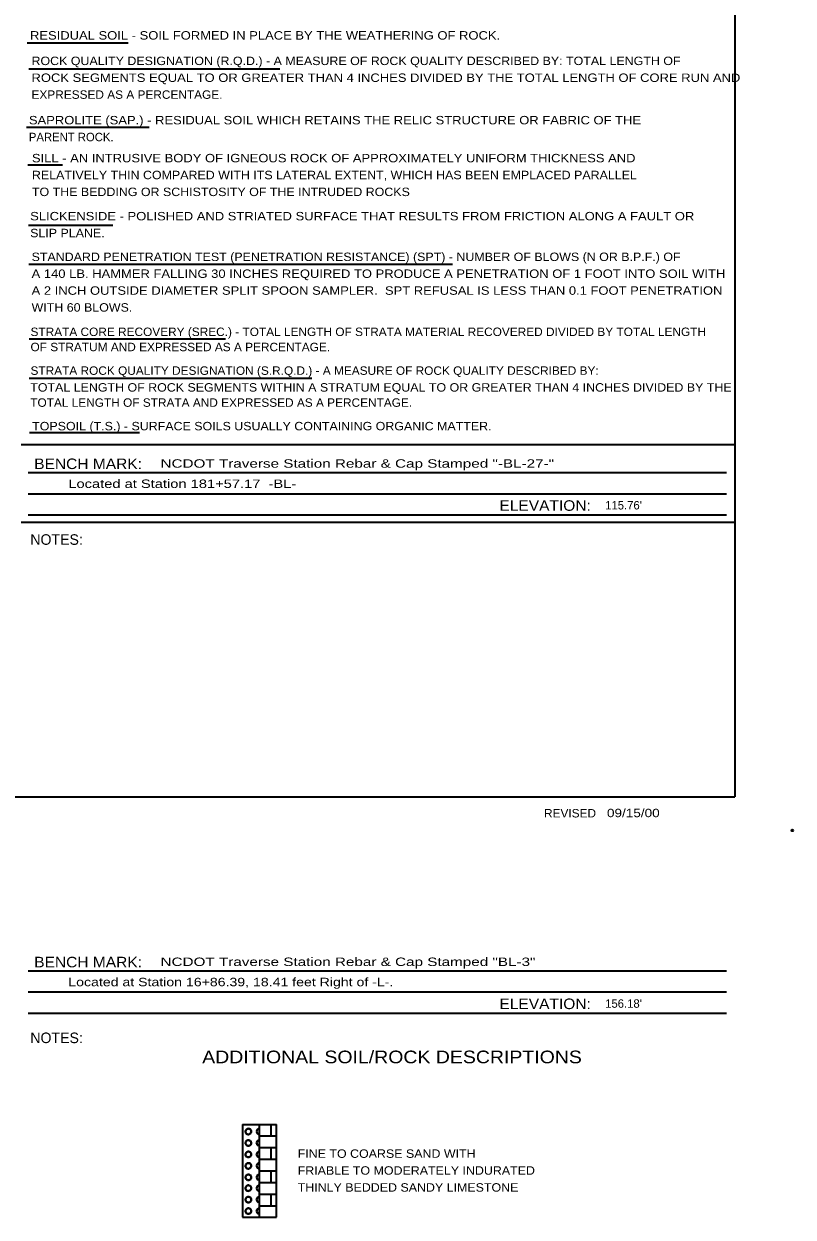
# Model space of a CAD drawing. Extents: x 2137492.6 to 2137529.1, y 2137475.8 to 2137563.
# Drawn here: x 2137519.94 to 2137529.06, y 2137534.75 to 2137548.89 of the extents above; entities that cross this region are included whole.
import ezdxf
from ezdxf.enums import TextEntityAlignment as Align

# ---------------------------------------------------------------- set-up
doc = ezdxf.new("R2010")
doc.units = 0
doc.header["$LTSCALE"] = 0.04
doc.header["$PDMODE"] = 32
doc.header["$PDSIZE"] = 0.02
doc.layers.add('1', color=7, linetype='Continuous', lineweight=35)
doc.layers.add('27', color=7, linetype='Continuous', lineweight=40)

msp = doc.modelspace()

# ---------------------------------------------------------------- linework, layer by layer
at = {"layer": '1'}
for p, q in [((2137528.371, 2137561.718), (2137528.371, 2137539.727)), ((2137528.371, 2137558.425), (2137528.371, 2137539.727)), ((2137519.985, 2137548.666), (2137521.181, 2137548.666)), ((2137520.003, 2137548.359), (2137522.976, 2137548.359)), ((2137519.977, 2137547.665), (2137521.431, 2137547.665)), ((2137519.993, 2137547.219), (2137520.402, 2137547.219)), ((2137519.998, 2137546.504), (2137521, 2137546.504)), ((2137520.003, 2137546.04), (2137525.022, 2137546.04)), ((2137520.008, 2137545.156), (2137522.335, 2137545.156)), ((2137520.006, 2137544.692), (2137523.357, 2137544.692)), ((2137520.011, 2137544.048), (2137521.314, 2137544.048)), ((2137519.912, 2137543.903), (2137528.371, 2137543.903)), ((2137519.994, 2137543.571), (2137528.27, 2137543.571)), ((2137519.994, 2137543.321), (2137528.27, 2137543.321)), ((2137519.912, 2137542.983), (2137528.371, 2137542.983)), ((2137519.994, 2137543.071), (2137528.27, 2137543.071)), ((2137519.994, 2137537.664), (2137528.27, 2137537.664)), ((2137519.994, 2137537.414), (2137528.27, 2137537.414)), ((2137519.994, 2137537.164), (2137528.27, 2137537.164)), ((2137522.537, 2137535.845), (2137522.937, 2137535.845)), ((2137522.537, 2137535.845), (2137522.537, 2137534.745)), ((2137522.737, 2137534.745), (2137522.737, 2137535.845)), ((2137522.875, 2137535.707), (2137522.875, 2137535.845)), ((2137522.937, 2137534.745), (2137522.937, 2137535.845)), ((2137522.737, 2137535.707), (2137522.937, 2137535.707)), ((2137522.737, 2137535.569), (2137522.937, 2137535.569)), ((2137522.875, 2137535.432), (2137522.875, 2137535.569)), ((2137522.737, 2137535.432), (2137522.937, 2137535.432)), ((2137522.737, 2137535.294), (2137522.937, 2137535.294)), ((2137522.875, 2137535.156), (2137522.875, 2137535.294)), ((2137522.737, 2137535.156), (2137522.937, 2137535.156)), ((2137522.737, 2137535.018), (2137522.937, 2137535.018)), ((2137522.875, 2137534.88), (2137522.875, 2137535.018)), ((2137522.737, 2137534.88), (2137522.937, 2137534.88)), ((2137522.537, 2137534.745), (2137522.937, 2137534.745))]:
    msp.add_line(p, q, dxfattribs=at)
msp.add_lwpolyline([(2137493.171, 2137561.718), (2137493.171, 2137539.727), (2137528.371, 2137539.727)], dxfattribs=at)
msp.add_point((2137529.05, 2137539.329), dxfattribs=at)
at = {"layer": '27'}
for points in [[(2137522.639, 2137535.76), (2137522.638, 2137535.765), (2137522.637, 2137535.77), (2137522.635, 2137535.775), (2137522.632, 2137535.78), (2137522.629, 2137535.784), (2137522.625, 2137535.787), (2137522.62, 2137535.79), (2137522.615, 2137535.792), (2137522.61, 2137535.793), (2137522.605, 2137535.794), (2137522.6, 2137535.793), (2137522.595, 2137535.792), (2137522.59, 2137535.79), (2137522.585, 2137535.787), (2137522.581, 2137535.784), (2137522.578, 2137535.78), (2137522.575, 2137535.776), (2137522.573, 2137535.771), (2137522.571, 2137535.766), (2137522.571, 2137535.76), (2137522.571, 2137535.755), (2137522.572, 2137535.75), (2137522.574, 2137535.745), (2137522.577, 2137535.74), (2137522.58, 2137535.736), (2137522.584, 2137535.733), (2137522.589, 2137535.73), (2137522.593, 2137535.728), (2137522.599, 2137535.726), (2137522.604, 2137535.726), (2137522.609, 2137535.726), (2137522.614, 2137535.727), (2137522.619, 2137535.729), (2137522.624, 2137535.732), (2137522.628, 2137535.735), (2137522.632, 2137535.739), (2137522.634, 2137535.743), (2137522.637, 2137535.748), (2137522.638, 2137535.753), (2137522.639, 2137535.759)], [(2137522.639, 2137535.624), (2137522.638, 2137535.629), (2137522.637, 2137535.634), (2137522.635, 2137535.639), (2137522.632, 2137535.644), (2137522.629, 2137535.648), (2137522.625, 2137535.651), (2137522.62, 2137535.654), (2137522.615, 2137535.656), (2137522.61, 2137535.657), (2137522.605, 2137535.658), (2137522.6, 2137535.658), (2137522.595, 2137535.656), (2137522.59, 2137535.654), (2137522.585, 2137535.652), (2137522.581, 2137535.648), (2137522.578, 2137535.644), (2137522.575, 2137535.64), (2137522.573, 2137535.635), (2137522.571, 2137535.63), (2137522.571, 2137535.625), (2137522.571, 2137535.619), (2137522.572, 2137535.614), (2137522.574, 2137535.609), (2137522.577, 2137535.605), (2137522.58, 2137535.6), (2137522.584, 2137535.597), (2137522.589, 2137535.594), (2137522.593, 2137535.592), (2137522.599, 2137535.591), (2137522.604, 2137535.59), (2137522.609, 2137535.59), (2137522.614, 2137535.591), (2137522.619, 2137535.593), (2137522.624, 2137535.596), (2137522.628, 2137535.599), (2137522.632, 2137535.603), (2137522.634, 2137535.608), (2137522.637, 2137535.612), (2137522.638, 2137535.618), (2137522.639, 2137535.623)], [(2137522.639, 2137535.488), (2137522.638, 2137535.494), (2137522.637, 2137535.499), (2137522.635, 2137535.504), (2137522.632, 2137535.508), (2137522.629, 2137535.512), (2137522.625, 2137535.516), (2137522.62, 2137535.518), (2137522.615, 2137535.52), (2137522.61, 2137535.522), (2137522.605, 2137535.522), (2137522.6, 2137535.522), (2137522.595, 2137535.521), (2137522.59, 2137535.519), (2137522.585, 2137535.516), (2137522.581, 2137535.513), (2137522.578, 2137535.509), (2137522.575, 2137535.504), (2137522.573, 2137535.499), (2137522.571, 2137535.494), (2137522.571, 2137535.489), (2137522.571, 2137535.484), (2137522.572, 2137535.478), (2137522.574, 2137535.473), (2137522.577, 2137535.469), (2137522.58, 2137535.465), (2137522.584, 2137535.461), (2137522.589, 2137535.458), (2137522.593, 2137535.456), (2137522.599, 2137535.455), (2137522.604, 2137535.454), (2137522.609, 2137535.455), (2137522.614, 2137535.456), (2137522.619, 2137535.458), (2137522.624, 2137535.46), (2137522.628, 2137535.463), (2137522.632, 2137535.467), (2137522.634, 2137535.472), (2137522.637, 2137535.477), (2137522.638, 2137535.482), (2137522.639, 2137535.487)], [(2137522.639, 2137535.352), (2137522.638, 2137535.358), (2137522.637, 2137535.363), (2137522.635, 2137535.368), (2137522.632, 2137535.372), (2137522.629, 2137535.376), (2137522.625, 2137535.38), (2137522.62, 2137535.383), (2137522.615, 2137535.385), (2137522.61, 2137535.386), (2137522.605, 2137535.386), (2137522.6, 2137535.386), (2137522.595, 2137535.385), (2137522.59, 2137535.383), (2137522.585, 2137535.38), (2137522.581, 2137535.377), (2137522.578, 2137535.373), (2137522.575, 2137535.368), (2137522.573, 2137535.363), (2137522.571, 2137535.358), (2137522.571, 2137535.353), (2137522.571, 2137535.348), (2137522.572, 2137535.343), (2137522.574, 2137535.338), (2137522.577, 2137535.333), (2137522.58, 2137535.329), (2137522.584, 2137535.325), (2137522.589, 2137535.323), (2137522.593, 2137535.32), (2137522.599, 2137535.319), (2137522.604, 2137535.319), (2137522.609, 2137535.319), (2137522.614, 2137535.32), (2137522.619, 2137535.322), (2137522.624, 2137535.324), (2137522.628, 2137535.328), (2137522.632, 2137535.332), (2137522.634, 2137535.336), (2137522.637, 2137535.341), (2137522.638, 2137535.346), (2137522.639, 2137535.351)], [(2137522.639, 2137535.217), (2137522.638, 2137535.222), (2137522.637, 2137535.227), (2137522.635, 2137535.232), (2137522.632, 2137535.237), (2137522.629, 2137535.241), (2137522.625, 2137535.244), (2137522.62, 2137535.247), (2137522.615, 2137535.249), (2137522.61, 2137535.25), (2137522.605, 2137535.251), (2137522.6, 2137535.25), (2137522.595, 2137535.249), (2137522.59, 2137535.247), (2137522.585, 2137535.244), (2137522.581, 2137535.241), (2137522.578, 2137535.237), (2137522.575, 2137535.233), (2137522.573, 2137535.228), (2137522.571, 2137535.223), (2137522.571, 2137535.217), (2137522.571, 2137535.212), (2137522.572, 2137535.207), (2137522.574, 2137535.202), (2137522.577, 2137535.197), (2137522.58, 2137535.193), (2137522.584, 2137535.19), (2137522.589, 2137535.187), (2137522.593, 2137535.185), (2137522.599, 2137535.183), (2137522.604, 2137535.183), (2137522.609, 2137535.183), (2137522.614, 2137535.184), (2137522.619, 2137535.186), (2137522.624, 2137535.189), (2137522.628, 2137535.192), (2137522.632, 2137535.196), (2137522.634, 2137535.2), (2137522.637, 2137535.205), (2137522.638, 2137535.21), (2137522.639, 2137535.216)], [(2137522.639, 2137535.088), (2137522.638, 2137535.094), (2137522.637, 2137535.099), (2137522.635, 2137535.104), (2137522.632, 2137535.108), (2137522.629, 2137535.112), (2137522.625, 2137535.116), (2137522.62, 2137535.118), (2137522.615, 2137535.12), (2137522.61, 2137535.122), (2137522.605, 2137535.122), (2137522.6, 2137535.122), (2137522.595, 2137535.121), (2137522.59, 2137535.119), (2137522.585, 2137535.116), (2137522.581, 2137535.113), (2137522.578, 2137535.109), (2137522.575, 2137535.104), (2137522.573, 2137535.099), (2137522.571, 2137535.094), (2137522.571, 2137535.089), (2137522.571, 2137535.084), (2137522.572, 2137535.078), (2137522.574, 2137535.073), (2137522.577, 2137535.069), (2137522.58, 2137535.065), (2137522.584, 2137535.061), (2137522.589, 2137535.058), (2137522.593, 2137535.056), (2137522.599, 2137535.055), (2137522.604, 2137535.054), (2137522.609, 2137535.055), (2137522.614, 2137535.056), (2137522.619, 2137535.058), (2137522.624, 2137535.06), (2137522.628, 2137535.063), (2137522.632, 2137535.067), (2137522.634, 2137535.072), (2137522.637, 2137535.077), (2137522.638, 2137535.082), (2137522.639, 2137535.087)], [(2137522.639, 2137534.952), (2137522.638, 2137534.958), (2137522.637, 2137534.963), (2137522.635, 2137534.968), (2137522.632, 2137534.972), (2137522.629, 2137534.976), (2137522.625, 2137534.98), (2137522.62, 2137534.983), (2137522.615, 2137534.985), (2137522.61, 2137534.986), (2137522.605, 2137534.986), (2137522.6, 2137534.986), (2137522.595, 2137534.985), (2137522.59, 2137534.983), (2137522.585, 2137534.98), (2137522.581, 2137534.977), (2137522.578, 2137534.973), (2137522.575, 2137534.968), (2137522.573, 2137534.963), (2137522.571, 2137534.958), (2137522.571, 2137534.953), (2137522.571, 2137534.948), (2137522.572, 2137534.943), (2137522.574, 2137534.938), (2137522.577, 2137534.933), (2137522.58, 2137534.929), (2137522.584, 2137534.925), (2137522.589, 2137534.923), (2137522.593, 2137534.92), (2137522.599, 2137534.919), (2137522.604, 2137534.919), (2137522.609, 2137534.919), (2137522.614, 2137534.92), (2137522.619, 2137534.922), (2137522.624, 2137534.924), (2137522.628, 2137534.928), (2137522.632, 2137534.932), (2137522.634, 2137534.936), (2137522.637, 2137534.941), (2137522.638, 2137534.946), (2137522.639, 2137534.951)], [(2137522.639, 2137534.817), (2137522.638, 2137534.822), (2137522.637, 2137534.827), (2137522.635, 2137534.832), (2137522.632, 2137534.837), (2137522.629, 2137534.841), (2137522.625, 2137534.844), (2137522.62, 2137534.847), (2137522.615, 2137534.849), (2137522.61, 2137534.85), (2137522.605, 2137534.851), (2137522.6, 2137534.85), (2137522.595, 2137534.849), (2137522.59, 2137534.847), (2137522.585, 2137534.844), (2137522.581, 2137534.841), (2137522.578, 2137534.837), (2137522.575, 2137534.833), (2137522.573, 2137534.828), (2137522.571, 2137534.823), (2137522.571, 2137534.817), (2137522.571, 2137534.812), (2137522.572, 2137534.807), (2137522.574, 2137534.802), (2137522.577, 2137534.797), (2137522.58, 2137534.793), (2137522.584, 2137534.79), (2137522.589, 2137534.787), (2137522.593, 2137534.785), (2137522.599, 2137534.783), (2137522.604, 2137534.783), (2137522.609, 2137534.783), (2137522.614, 2137534.784), (2137522.619, 2137534.786), (2137522.624, 2137534.789), (2137522.628, 2137534.792), (2137522.632, 2137534.796), (2137522.634, 2137534.8), (2137522.637, 2137534.805), (2137522.638, 2137534.81), (2137522.639, 2137534.816)]]:
    msp.add_lwpolyline(points, close=True, dxfattribs=at)
for points in [[(2137522.737, 2137535.794), (2137522.732, 2137535.793), (2137522.727, 2137535.792), (2137522.722, 2137535.79), (2137522.718, 2137535.787), (2137522.713, 2137535.784), (2137522.71, 2137535.78), (2137522.707, 2137535.776), (2137522.705, 2137535.771), (2137522.704, 2137535.766), (2137522.703, 2137535.76), (2137522.704, 2137535.755), (2137522.705, 2137535.75), (2137522.707, 2137535.745), (2137522.709, 2137535.74), (2137522.713, 2137535.736), (2137522.717, 2137535.733), (2137522.721, 2137535.73), (2137522.726, 2137535.728), (2137522.731, 2137535.726), (2137522.736, 2137535.726), (2137522.737, 2137535.726)], [(2137522.737, 2137535.658), (2137522.732, 2137535.658), (2137522.727, 2137535.656), (2137522.722, 2137535.654), (2137522.718, 2137535.652), (2137522.713, 2137535.648), (2137522.71, 2137535.644), (2137522.707, 2137535.64), (2137522.705, 2137535.635), (2137522.704, 2137535.63), (2137522.703, 2137535.625), (2137522.704, 2137535.619), (2137522.705, 2137535.614), (2137522.707, 2137535.609), (2137522.709, 2137535.605), (2137522.713, 2137535.6), (2137522.717, 2137535.597), (2137522.721, 2137535.594), (2137522.726, 2137535.592), (2137522.731, 2137535.591), (2137522.736, 2137535.59), (2137522.737, 2137535.59)], [(2137522.737, 2137535.522), (2137522.732, 2137535.522), (2137522.727, 2137535.521), (2137522.722, 2137535.519), (2137522.718, 2137535.516), (2137522.713, 2137535.513), (2137522.71, 2137535.509), (2137522.707, 2137535.504), (2137522.705, 2137535.499), (2137522.704, 2137535.494), (2137522.703, 2137535.489), (2137522.704, 2137535.484), (2137522.705, 2137535.478), (2137522.707, 2137535.473), (2137522.709, 2137535.469), (2137522.713, 2137535.465), (2137522.717, 2137535.461), (2137522.721, 2137535.458), (2137522.726, 2137535.456), (2137522.731, 2137535.455), (2137522.736, 2137535.454), (2137522.737, 2137535.454)], [(2137522.737, 2137535.386), (2137522.732, 2137535.386), (2137522.727, 2137535.385), (2137522.722, 2137535.383), (2137522.718, 2137535.38), (2137522.713, 2137535.377), (2137522.71, 2137535.373), (2137522.707, 2137535.368), (2137522.705, 2137535.363), (2137522.704, 2137535.358), (2137522.703, 2137535.353), (2137522.704, 2137535.348), (2137522.705, 2137535.343), (2137522.707, 2137535.338), (2137522.709, 2137535.333), (2137522.713, 2137535.329), (2137522.717, 2137535.325), (2137522.721, 2137535.323), (2137522.726, 2137535.32), (2137522.731, 2137535.319), (2137522.736, 2137535.319), (2137522.737, 2137535.319)], [(2137522.737, 2137535.251), (2137522.732, 2137535.25), (2137522.727, 2137535.249), (2137522.722, 2137535.247), (2137522.718, 2137535.244), (2137522.713, 2137535.241), (2137522.71, 2137535.237), (2137522.707, 2137535.233), (2137522.705, 2137535.228), (2137522.704, 2137535.223), (2137522.703, 2137535.217), (2137522.704, 2137535.212), (2137522.705, 2137535.207), (2137522.707, 2137535.202), (2137522.709, 2137535.197), (2137522.713, 2137535.193), (2137522.717, 2137535.19), (2137522.721, 2137535.187), (2137522.726, 2137535.185), (2137522.731, 2137535.183), (2137522.736, 2137535.183), (2137522.737, 2137535.183)], [(2137522.737, 2137535.122), (2137522.732, 2137535.122), (2137522.727, 2137535.121), (2137522.722, 2137535.119), (2137522.718, 2137535.116), (2137522.713, 2137535.113), (2137522.71, 2137535.109), (2137522.707, 2137535.104), (2137522.705, 2137535.099), (2137522.704, 2137535.094), (2137522.703, 2137535.089), (2137522.704, 2137535.084), (2137522.705, 2137535.078), (2137522.707, 2137535.073), (2137522.709, 2137535.069), (2137522.713, 2137535.065), (2137522.717, 2137535.061), (2137522.721, 2137535.058), (2137522.726, 2137535.056), (2137522.731, 2137535.055), (2137522.736, 2137535.054), (2137522.737, 2137535.054)], [(2137522.737, 2137534.986), (2137522.732, 2137534.986), (2137522.727, 2137534.985), (2137522.722, 2137534.983), (2137522.718, 2137534.98), (2137522.713, 2137534.977), (2137522.71, 2137534.973), (2137522.707, 2137534.968), (2137522.705, 2137534.963), (2137522.704, 2137534.958), (2137522.703, 2137534.953), (2137522.704, 2137534.948), (2137522.705, 2137534.943), (2137522.707, 2137534.938), (2137522.709, 2137534.933), (2137522.713, 2137534.929), (2137522.717, 2137534.925), (2137522.721, 2137534.923), (2137522.726, 2137534.92), (2137522.731, 2137534.919), (2137522.736, 2137534.919), (2137522.737, 2137534.919)], [(2137522.737, 2137534.851), (2137522.732, 2137534.85), (2137522.727, 2137534.849), (2137522.722, 2137534.847), (2137522.718, 2137534.844), (2137522.713, 2137534.841), (2137522.71, 2137534.837), (2137522.707, 2137534.833), (2137522.705, 2137534.828), (2137522.704, 2137534.823), (2137522.703, 2137534.817), (2137522.704, 2137534.812), (2137522.705, 2137534.807), (2137522.707, 2137534.802), (2137522.709, 2137534.797), (2137522.713, 2137534.793), (2137522.717, 2137534.79), (2137522.721, 2137534.787), (2137522.726, 2137534.785), (2137522.731, 2137534.783), (2137522.736, 2137534.783), (2137522.737, 2137534.783)]]:
    msp.add_lwpolyline(points, dxfattribs=at)

# ---------------------------------------------------------------- texts
at = {"layer": '1'}
for s, height, width, p in [('RESIDUAL SOIL - SOIL FORMED IN PLACE BY THE WEATHERING OF ROCK.', 0.1, 1.15, (2137520.017, 2137548.704)), ('ROCK QUALITY DESIGNATION (R.Q.D.) - A MEASURE OF ROCK QUALITY DESCRIBED BY: TOTAL LENGTH OF ', 0.1, 1.1, (2137520.035, 2137548.402)), ('ROCK SEGMENTS EQUAL TO OR GREATER THAN 4 INCHES DIVIDED BY THE TOTAL LENGTH OF CORE RUN AND ', 0.1, 1.15, (2137520.035, 2137548.202)), ('EXPRESSED AS A PERCENTAGE.', 0.1, 1.05, (2137520.035, 2137548.002)), ('SAPROLITE (SAP.) - RESIDUAL SOIL WHICH RETAINS THE RELIC STRUCTURE OR FABRIC OF THE ', 0.1, 1.15, (2137520.004, 2137547.699)), ('SILL - AN INTRUSIVE BODY OF IGNEOUS ROCK OF APPROXIMATELY UNIFORM THICKNESS AND', 0.1, 1.15, (2137520.04, 2137547.249)), ('RELATIVELY THIN COMPARED WITH ITS LATERAL EXTENT, WHICH HAS BEEN EMPLACED PARALLEL', 0.1, 1.1, (2137520.04, 2137547.049)), ('TO THE BEDDING OR SCHISTOSITY OF THE INTRUDED ROCKS', 0.1, 1.1, (2137520.04, 2137546.849)), ('SLICKENSIDE - POLISHED AND STRIATED SURFACE THAT RESULTS FROM FRICTION ALONG A FAULT OR ', 0.1, 1.15, (2137520.019, 2137546.561)), ('SLIP PLANE.', 0.1, 1.1, (2137520.019, 2137546.361)), ('STANDARD PENETRATION TEST (PENETRATION RESISTANCE) (SPT) - NUMBER OF BLOWS (N OR B.P.F.) OF ', 0.1, 1.1, (2137520.036, 2137546.079)), ('A 140 LB. HAMMER FALLING 30 INCHES REQUIRED TO PRODUCE A PENETRATION OF 1 FOOT INTO SOIL WITH ', 0.1, 1.15, (2137520.036, 2137545.879)), ('A 2 INCH OUTSIDE DIAMETER SPLIT SPOON SAMPLER.  SPT REFUSAL IS LESS THAN 0.1 FOOT PENETRATION ', 0.1, 1.15, (2137520.036, 2137545.679)), ('WITH 60 BLOWS.', 0.1, 1.1, (2137520.036, 2137545.479)), ('STRATA CORE RECOVERY (SREC.) - TOTAL LENGTH OF STRATA MATERIAL RECOVERED DIVIDED BY TOTAL LENGTH', 0.1, 1.05, (2137520.023, 2137545.19)), ('OF STRATUM AND EXPRESSED AS A PERCENTAGE.', 0.1, 1.05, (2137520.023, 2137545.01)), ('STRATA ROCK QUALITY DESIGNATION (S.R.Q.D.) - A MEASURE OF ROCK QUALITY DESCRIBED BY:', 0.1, 1.05, (2137520.023, 2137544.73)), ('TOTAL LENGTH OF ROCK SEGMENTS WITHIN A STRATUM EQUAL TO OR GREATER THAN 4 INCHES DIVIDED BY THE', 0.1, 1.1, (2137520.02, 2137544.531)), ('TOTAL LENGTH OF STRATA AND EXPRESSED AS A PERCENTAGE.', 0.1, 1.05, (2137520.02, 2137544.351)), ('TOPSOIL (T.S.) - SURFACE SOILS USUALLY CONTAINING ORGANIC MATTER.', 0.1, 1.1, (2137520.043, 2137544.072)), ('BENCH MARK:', 0.125, 1.1, (2137520.067, 2137543.613)), ('NCDOT Traverse Station Rebar & Cap Stamped "-BL-27-"', 0.1, 1.35, (2137521.564, 2137543.629)), ('Located at Station 181+57.17  -BL-', 0.1, 1.3, (2137520.471, 2137543.389)), ('ELEVATION:', 0.125, 1.1, (2137525.58, 2137543.118)), ('REVISED ', 0.1, 1.05, (2137526.108, 2137539.483)), ('09/15/00', 0.1, 1.2, (2137526.854, 2137539.486)), ('BENCH MARK:', 0.125, 1.1, (2137520.067, 2137537.706)), ('NCDOT Traverse Station Rebar & Cap Stamped "BL-3"', 0.1, 1.35, (2137521.564, 2137537.722)), ('Located at Station 16+86.39, 18.41 feet Right of -L-.', 0.1, 1.25, (2137520.471, 2137537.482)), ('ELEVATION:', 0.125, 1.1, (2137525.58, 2137537.211)), ('FINE TO COARSE SAND WITH', 0.1, 1.1, (2137523.189, 2137535.448)), ('FRIABLE TO MODERATELY INDURATED', 0.1, 1.1, (2137523.189, 2137535.248)), ('THINLY BEDDED SANDY LIMESTONE', 0.1, 1.1, (2137523.189, 2137535.047))]:
    msp.add_text(s, height=height, dxfattribs=dict(at, width=width)).set_placement(p)
for s, height, p in [('PARENT ROCK.', 0.1, (2137520.004, 2137547.499)), ("115.76'", 0.1, (2137526.833, 2137543.134)), ('NOTES:', 0.125, (2137520.021, 2137542.715)), ("156.18'", 0.1, (2137526.833, 2137537.227)), ('NOTES:', 0.125, (2137520.021, 2137536.808))]:
    msp.add_text(s, height=height, dxfattribs=at).set_placement(p)
at = {"layer": '1', "width": 1.15}
msp.add_text('ADDITIONAL SOIL/ROCK DESCRIPTIONS', height=0.15, dxfattribs=at).set_placement((2137524.307, 2137536.569), align=Align.CENTER)

doc.saveas('drawing.dxf')
